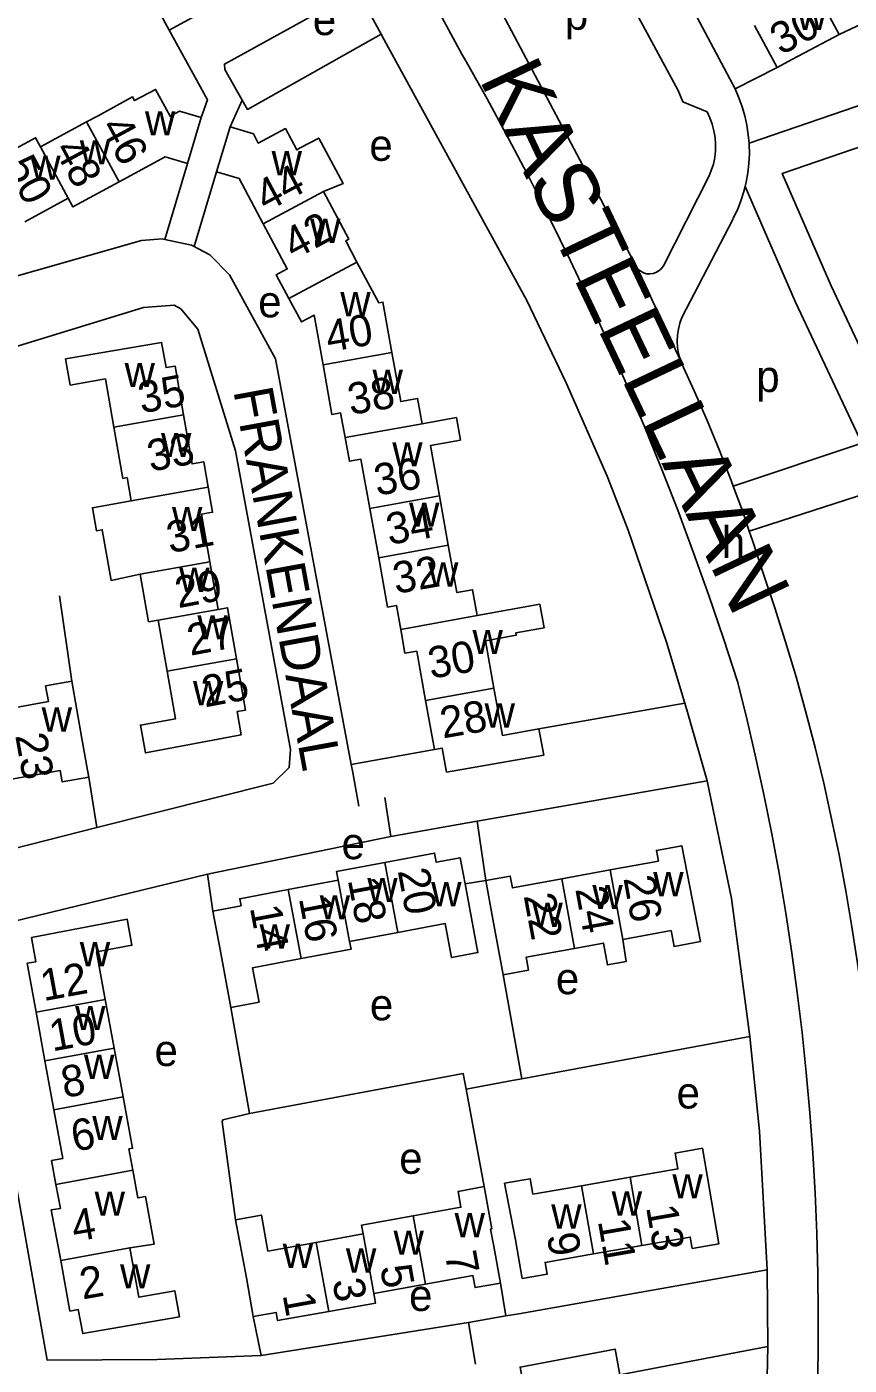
# Model space of a CAD drawing. Extents: x 157794 to 159375, y 380877 to 382306.
# Drawn here: x 158902.6 to 159007.2, y 381561.1 to 381731.3 of the extents above; entities that cross this region are included whole.
import ezdxf

# ---------------------------------------------------------------- set-up
doc = ezdxf.new("R2010")
doc.units = 0
for name, color, linetype in [('BLT_Basislijn', 7, 'Continuous'), ('BLT_Bebouwing', 7, 'Continuous'), ('BLT_Centroide', 7, 'Continuous'), ('BLT_Huisnummer', 7, 'Continuous'), ('BLT_Huisnummer_ tussenligend', 7, 'Continuous'), ('BLT_Onderverdeling_panden', 7, 'Continuous'), ('BLT_Straatnaam', 7, 'Continuous'), ('BLT_Straatnaam_hoofdweg', 7, 'Continuous'), ('BLT_Vlakafsluiter', 7, 'Continuous')]:
    doc.layers.add(name, color=color, linetype=linetype)

msp = doc.modelspace()

# ---------------------------------------------------------------- linework, layer by layer
at = {"layer": 'BLT_Basislijn'}
for p, q in [((158945.98, 381750), (158957.93, 381727.86)), ((158985.45, 381723.23), (158970.96, 381750)), ((158978.56, 381750), (158992.69, 381723.42)), ((158947.67, 381730.38), (158937.97, 381748.31)), ((159073.46, 381743.61), (158994.46, 381716.52)), ((158961.79, 381735.49), (158980.12, 381700.78)), ((159005.91, 381730.36), (159018.4, 381736.22)), ((158948.05, 381729.68), (158947.67, 381730.38)), ((158998.02, 381726.14), (158992.69, 381723.42)), ((158928.45, 381718.59), (158929.96, 381722.01)), ((158920.13, 381704.27), (158923, 381713.94)), ((158923.86, 381703.37), (158926.71, 381712.88)), ((158983.58, 381700.92), (158989.39, 381712.38)), ((158992.39, 381706.83), (158985.92, 381694.34)), ((159008.8, 381678.36), (158992.46, 381672.87)), ((159010.76, 381672.41), (158994.49, 381667.18)), ((158906.74, 381658.94), (158908.28, 381648.08)), ((158967.73, 381642.01), (158986.28, 381645.29)), ((158943.84, 381637.49), (158954.43, 381639.37)), ((158910.44, 381635.86), (158911.49, 381629.45)), ((158959.88, 381630.28), (158989.13, 381635.38)), ((158948.12, 381633.27), (158948.9, 381628.3)), ((158960.95, 381622.7), (158959.88, 381630.28)), ((158948.9, 381628.3), (158925.56, 381623.52)), ((158925.56, 381623.52), (158926.23, 381618.83)), ((158958.32, 381622.28), (158960.95, 381622.7)), ((158963.16, 381610.71), (158965.54, 381597.49)), ((158928.54, 381606.57), (158930.9, 381593.06)), ((158994.57, 381602.88), (158965.54, 381597.49)), ((158958.47, 381596.15), (158960.77, 381583.77)), ((158996.87, 381563.43), (158996.78, 381573.19)), ((158962.82, 381571.5), (158963.53, 381567.32)), ((158932.38, 381562.28), (158931.38, 381567.24)), ((158958.78, 381566.5), (158963.53, 381567.32)), ((158932.38, 381562.28), (158958.78, 381566.5)), ((158959.66, 381561.2), (158958.78, 381566.5)), ((158978.02, 381559.82), (158996.87, 381563.43))]:
    msp.add_line(p, q, dxfattribs=at)
for points in [[(159108.87, 381686.54), (159105.46, 381699.16), (159100.87, 381714.75), (159096.96, 381727.42), (159090, 381741.34), (159089.57, 381741.73), (159089.09, 381742.06), (159088.58, 381742.33), (159088.02, 381742.52), (159087.45, 381742.63), (159086.87, 381742.66), (159086.29, 381742.62), (159085.72, 381742.49), (159085.49, 381742.42), (159084.45, 381742.09), (158998.68, 381712.68), (159004.91, 381698.37), (159013.56, 381679.97)], [(158937.34, 381739.97), (158939.99, 381734.95), (158940.67, 381733.68), (158927.71, 381726.58), (158927.76, 381725.9), (158929.96, 381722.01)], [(158847.29, 381733.34), (158870.18, 381690.77), (158917.15, 381704.15), (158919.77, 381704.34), (158920.13, 381704.27)], [(158924.74, 381719.79), (158925.55, 381722.03), (158920.68, 381730.91)], [(158929.96, 381722.01), (158930.64, 381720.81), (158947.67, 381730.38)], [(158948.05, 381729.68), (158966.18, 381696.49), (158971.19, 381686.04), (158976.39, 381674.17), (158979.06, 381667.27), (158983.95, 381653.06), (158986.28, 381645.29)], [(158993.01, 381648.03), (158991.22, 381653.51), (158989.35, 381658.98), (158987.4, 381664.41), (158985.38, 381669.82), (158983.28, 381675.2), (158981.11, 381680.55), (158978.87, 381685.87), (158976.55, 381691.16), (158974.16, 381696.42), (158971.69, 381701.64), (158969.16, 381706.83), (158966.55, 381711.98), (158963.87, 381717.1), (158961.12, 381722.18), (158958.3, 381727.22), (158957.93, 381727.86)], [(158992.69, 381723.42), (158993.18, 381722.31), (158993.59, 381721.16), (158993.93, 381719.99), (158994.19, 381718.8), (158994.37, 381717.6), (158994.46, 381716.52)], [(158985.45, 381723.23), (158986.04, 381721.76), (158989.12, 381720.5)], [(158989.12, 381720.5), (158989.49, 381719.73), (158989.78, 381718.92), (158990, 381718.1), (158990.15, 381717.25), (158990.21, 381716.4), (158990.19, 381715.55), (158990.09, 381714.7), (158989.92, 381713.86), (158989.66, 381713.04), (158989.39, 381712.38)], [(158994.46, 381716.52), (158994.48, 381716.38), (158994.5, 381715.16), (158994.44, 381713.95), (158994.3, 381712.74), (158994.09, 381711.54), (158993.95, 381711)], [(158993.95, 381711), (158993.79, 381710.36), (158993.42, 381709.2), (158992.98, 381708.06), (158992.46, 381706.96), (158992.39, 381706.83)], [(158993.95, 381711), (159000.36, 381696.3), (159008.8, 381678.36)], [(158920.13, 381704.27), (158923.51, 381703.56), (158923.86, 381703.37)], [(158923.86, 381703.37), (158924.33, 381703.11), (158925.87, 381702.32), (158928.35, 381699.78), (158934.21, 381689.08), (158943.84, 381637.49)], [(158980.12, 381700.78), (158980.37, 381700.47), (158980.69, 381700.22), (158981.05, 381700.03), (158981.43, 381699.92), (158981.84, 381699.89), (158982.24, 381699.93), (158982.62, 381700.06), (158982.97, 381700.26), (158983.28, 381700.52), (158983.58, 381700.92)], [(158894.53, 381688.61), (158917.4, 381695.62), (158921.29, 381695.91), (158922.18, 381695.43), (158924.34, 381692.84), (158929.11, 381677.4), (158936.12, 381639.38), (158935.96, 381637.09), (158933.89, 381635.11), (158911.49, 381629.45)], [(158985.92, 381694.34), (158985.66, 381693.61), (158985.47, 381692.85), (158985.35, 381692.08), (158985.32, 381691.3), (158985.37, 381690.52), (158985.5, 381689.75), (158985.7, 381689), (158985.78, 381688.79)], [(158985.78, 381688.79), (158985.99, 381688.27), (158986.11, 381688)], [(158992.46, 381672.87), (158992.19, 381673.6), (158990.7, 381677.43), (158989.12, 381681.23), (158987.48, 381685), (158986.11, 381688)], [(158994.49, 381667.18), (158993.61, 381669.74), (158992.46, 381672.87)], [(158996.23, 381661.94), (158994.96, 381665.85), (158994.49, 381667.18)], [(158996.23, 381661.94), (158997.71, 381657.52), (158999.11, 381653.08), (159000.44, 381648.62), (159001.69, 381644.13), (159002.86, 381639.62), (159003.96, 381635.1), (159004.97, 381630.55), (159005.91, 381625.99), (159006.77, 381621.42), (159007.56, 381616.83), (159008.26, 381612.22), (159008.88, 381607.61), (159009.43, 381602.98), (159009.89, 381598.35), (159010.28, 381593.71), (159010.58, 381589.06), (159010.81, 381584.41), (159010.95, 381579.75), (159011.02, 381575.1), (159011.01, 381570.44), (159010.91, 381565.79), (159010.74, 381561.13), (159010.55, 381557.62)], [(159001.42, 381531.85), (159001.92, 381536.94), (159002.35, 381542.05), (159002.69, 381547.15), (159002.96, 381552.26), (159003.14, 381557.38), (159003.25, 381562.5), (159003.27, 381567.61), (159003.22, 381572.73), (159003.08, 381577.85), (159002.87, 381582.96), (159002.58, 381588.07), (159002.2, 381593.18), (159001.75, 381598.28), (159001.21, 381603.37), (159000.6, 381608.45), (158999.91, 381613.52), (158999.14, 381618.58), (158998.29, 381623.63), (158997.36, 381628.66), (158996.35, 381633.68), (158995.26, 381638.68), (158994.1, 381643.67), (158993.01, 381648.03)], [(158986.28, 381645.29), (158986.63, 381644.13), (158989.13, 381635.38)], [(158944.82, 381632.16), (158944.03, 381636.47), (158943.84, 381637.49)], [(158989.13, 381635.38), (158992.21, 381620.43), (158994.57, 381602.88)], [(158948.9, 381628.3), (158958.65, 381630.07), (158959.88, 381630.28)], [(158911.49, 381629.45), (158894.11, 381625.06), (158890.08, 381622.32), (158888.54, 381620.61), (158886.95, 381616.56), (158886.84, 381611.22), (158889.4, 381597.76), (158889.65, 381596.38)], [(158925.56, 381623.52), (158895.74, 381616.26), (158896.49, 381610.43), (158905.17, 381561.69), (158919.14, 381561.76), (158932.38, 381562.28)], [(158996.78, 381573.19), (158995.81, 381590.81), (158994.57, 381602.88)], [(158958.47, 381596.15), (158958.1, 381598.15), (158930.9, 381593.06)], [(158958.47, 381596.15), (158964.33, 381597.27), (158965.54, 381597.49)], [(158930.9, 381593.06), (158927.52, 381592.29), (158927.42, 381592.03), (158929.1, 381579.55)], [(158963.53, 381567.32), (158965.16, 381567.6), (158996.78, 381573.19)], [(158993.58, 381507.56), (158996.46, 381546.02), (158996.87, 381563.43)]]:
    msp.add_lwpolyline(points, dxfattribs=at)
at = {"layer": 'BLT_Bebouwing'}
for p, q in [((158937.34, 381739.97), (158920.68, 381730.91)), ((158995.17, 381731.5), (158998.02, 381726.14)), ((158910.17, 381719.23), (158904.3, 381716.05)), ((158924.74, 381719.79), (158923, 381713.94)), ((158928.45, 381718.59), (158926.71, 381712.88)), ((158907.84, 381709.52), (158902.31, 381706.53)), ((158956.19, 381665.38), (158955.06, 381671.65)), ((158946.21, 381670.05), (158947.34, 381663.78)), ((158926.9, 381657.2), (158925.84, 381663.25)), ((158920.4, 381649.35), (158919.26, 381655.85)), ((158953.3, 381645.63), (158954.43, 381639.37)), ((158970.62, 381622.93), (158976.77, 381624.06)), ((158935.82, 381621.56), (158942.17, 381622.76)), ((158943.64, 381614.95), (158949.79, 381616.11)), ((158912.54, 381607.59), (158913.68, 381601.39)), ((158904.87, 381599.77), (158903.73, 381605.97)), ((158913.68, 381601.39), (158914.82, 381595.18)), ((158906.01, 381593.56), (158904.87, 381599.77)), ((158973.15, 381583.89), (158979.32, 381584.96)), ((158939.4, 381576.68), (158945.35, 381577.76)), ((158974.66, 381575.21), (158980.83, 381576.28)), ((158953.3, 381571.37), (158946.72, 381570.18))]:
    msp.add_line(p, q, dxfattribs=at)
for points in [[(158917.24, 381737.24), (158918.29, 381735.31), (158920.68, 381730.91)], [(159005.91, 381730.36), (159003.57, 381734.78), (159003.07, 381735.71)], [(158998.02, 381726.14), (159000, 381727.2), (159005.91, 381730.36)], [(158924.74, 381719.79), (158922, 381720.6), (158920.8, 381719.95), (158918.95, 381723.37), (158916.28, 381721.93), (158916.03, 381722.4), (158911.63, 381720.02), (158910.17, 381719.23)], [(158940.32, 381710.36), (158942.8, 381711.38), (158939.71, 381717.16), (158937.36, 381715.91), (158936.9, 381715.67), (158935.46, 381718.37), (158932.02, 381716.54), (158931.4, 381717.69), (158928.45, 381718.59)], [(158904.3, 381716.05), (158903.67, 381717.21), (158898.15, 381714.22)], [(158923, 381713.94), (158920.17, 381714.78), (158914.3, 381711.6)], [(158914.3, 381711.6), (158908.43, 381708.42), (158907.84, 381709.52)], [(158926.71, 381712.88), (158929.57, 381712.01), (158932.64, 381706.26)], [(158944.57, 381701.4), (158943.14, 381704.09), (158943.54, 381704.31), (158940.32, 381710.36)], [(158932.64, 381706.26), (158935.7, 381700.52), (158934.31, 381699.77), (158935.9, 381696.78)], [(158949.02, 381689.91), (158947.87, 381696.3), (158947.34, 381696.21), (158944.57, 381701.4)], [(158935.9, 381696.78), (158937.5, 381693.79), (158939.11, 381694.65), (158940.25, 381688.33)], [(158913.64, 381680.38), (158912.56, 381686.53), (158908.09, 381685.74), (158907.5, 381689.08), (158919.72, 381691.17), (158920.28, 381687.97), (158921.42, 381688.17), (158922.51, 381681.94)], [(158952.86, 381680.83), (158952.28, 381684.04), (158950.15, 381683.65), (158949.02, 381689.91)], [(158940.25, 381688.33), (158941.39, 381682), (158942.49, 381682.2), (158943.07, 381679.07)], [(158925.64, 381672.76), (158925.08, 381675.97), (158923.6, 381675.71), (158922.51, 381681.94)], [(158955.06, 381671.65), (158953.91, 381678.05), (158957.74, 381678.74), (158957.22, 381681.62), (158952.86, 381680.83)], [(158915.85, 381671.04), (158915.33, 381673.98), (158914.79, 381673.88), (158913.64, 381680.38)], [(158943.07, 381679.07), (158943.62, 381676.06), (158945.08, 381676.32), (158946.21, 381670.05)], [(158925.84, 381663.25), (158924.77, 381669.31), (158926.2, 381669.56), (158925.64, 381672.76)], [(158917, 381661.7), (158913.3, 381660.89), (158912.17, 381667.35), (158911.42, 381667.22), (158910.91, 381670.14), (158915.85, 381671.04)], [(158959.88, 381656.43), (158959.29, 381659.7), (158957.28, 381659.34), (158956.19, 381665.38)], [(158947.34, 381663.78), (158948.47, 381657.51), (158949.59, 381657.71), (158950.14, 381654.67)], [(158919.26, 381655.85), (158918.06, 381655.64), (158917, 381661.7)], [(158929.25, 381650.9), (158928.11, 381657.41), (158926.9, 381657.2)], [(158967.86, 381657.87), (158959.88, 381656.43)], [(158961.99, 381647.2), (158960.91, 381653.21), (158964.84, 381653.92), (158964.79, 381654.23), (158968.4, 381654.88), (158967.86, 381657.87)], [(158950.14, 381654.67), (158950.68, 381651.63), (158952.17, 381651.89), (158953.3, 381645.63)], [(158929.25, 381650.9), (158930.4, 381644.39), (158929.31, 381644.2), (158929.83, 381641.24), (158917.65, 381638.94), (158917.02, 381642.5), (158921.47, 381643.28), (158920.4, 381649.35)], [(158899.03, 381644.35), (158905.3, 381645.48), (158904.94, 381647.48), (158908.28, 381648.08)], [(158908.28, 381648.08), (158909.55, 381640.78), (158910.28, 381636.75), (158910.44, 381635.86)], [(158967.73, 381642.01), (158963.08, 381641.17), (158961.99, 381647.2)], [(158954.43, 381639.37), (158955.42, 381639.55), (158955.97, 381636.51), (158968.33, 381638.65), (158967.73, 381642.01)], [(158910.44, 381635.86), (158907.07, 381635.26), (158906.81, 381636.71), (158900.6, 381635.6)], [(158976.77, 381624.06), (158982.93, 381625.19), (158982.68, 381626.55), (158985.9, 381627.14), (158988.28, 381614.94), (158984.92, 381614.32), (158984.55, 381616.35), (158978.4, 381615.21)], [(158948.11, 381625.02), (158941.96, 381623.86), (158942.17, 381622.76)], [(158948.11, 381625.02), (158954.44, 381626.21), (158954.66, 381625.04), (158957.69, 381625.61), (158958.32, 381622.28)], [(158960.95, 381622.7), (158964.08, 381623.28), (158964.36, 381621.78), (158970.62, 381622.93)], [(158926.23, 381618.83), (158929.83, 381619.51), (158929.66, 381620.4), (158935.82, 381621.56)], [(158949.79, 381616.11), (158955.81, 381617.24), (158956.62, 381612.92), (158959.96, 381613.54), (158958.62, 381620.7), (158958.32, 381622.28)], [(158963.16, 381610.71), (158961.86, 381617.79), (158960.95, 381622.7)], [(158903.16, 381615.46), (158915.34, 381617.78), (158915.94, 381614.49), (158911.43, 381613.66), (158912.54, 381607.59)], [(158928.54, 381606.57), (158927.16, 381613.92), (158926.23, 381618.83)], [(158903.73, 381605.97), (158902.6, 381612.18), (158903.72, 381612.39), (158903.16, 381615.46)], [(158937.48, 381612.78), (158943.83, 381613.98), (158943.64, 381614.95)], [(158972.25, 381614.08), (158975.93, 381614.76), (158976.44, 381611.98), (158978.84, 381612.42), (158978.4, 381615.21)], [(158928.54, 381606.57), (158932.11, 381607.24), (158931.28, 381611.61), (158937.48, 381612.78)], [(158963.16, 381610.71), (158966.4, 381611.32), (158966.1, 381612.95), (158972.25, 381614.08)], [(158914.82, 381595.18), (158916.02, 381588.65), (158915.56, 381588.57), (158916.06, 381585.85)], [(158906.27, 381584.05), (158905.71, 381587.09), (158907.15, 381587.36), (158906.01, 381593.56)], [(158979.32, 381584.96), (158985.41, 381586.02), (158985.06, 381588.05), (158988.52, 381588.66), (158990.63, 381576.5), (158987.24, 381575.91), (158986.99, 381577.35), (158980.83, 381576.28)], [(158916.06, 381585.85), (158916.7, 381582.33), (158917.66, 381582.5), (158918.77, 381576.47), (158915.67, 381575.98)], [(158906.87, 381574.36), (158905.68, 381580.8), (158906.83, 381581.01), (158906.27, 381584.05)], [(158951.73, 381580.05), (158957.79, 381581.15), (158957.43, 381583.17), (158960.77, 381583.77)], [(158960.77, 381583.77), (158961.74, 381578.41), (158961.58, 381578.38), (158961.93, 381576.42), (158962.82, 381571.5)], [(158973.15, 381583.89), (158966.96, 381582.82), (158966.62, 381584.77), (158963.36, 381584.2), (158964.74, 381577.01), (158965.6, 381572.08)], [(158929.1, 381579.55), (158932.41, 381580.15), (158933.24, 381575.57), (158939.4, 381576.68)], [(158931.38, 381567.24), (158930.5, 381572.16), (158929.1, 381579.55)], [(158945.35, 381577.76), (158945.15, 381578.87), (158951.73, 381580.05)], [(158915.67, 381575.98), (158916.83, 381569.69), (158921.38, 381570.53), (158921.98, 381567.22), (158909.67, 381565.07), (158909.11, 381568.12), (158908.05, 381567.93), (158906.87, 381574.36)], [(158965.6, 381572.08), (158968.76, 381572.63), (158968.5, 381574.14), (158974.66, 381575.21)], [(158962.82, 381571.5), (158959.61, 381570.92), (158959.33, 381572.46), (158953.3, 381571.37)], [(158946.72, 381570.18), (158946.94, 381568.96), (158940.99, 381567.89)], [(158940.99, 381567.89), (158934.48, 381566.72), (158934.29, 381567.76), (158931.38, 381567.24)], [(158978.02, 381559.82), (158977.41, 381563.11), (158965.33, 381560.82), (158965.89, 381557.81), (158964.76, 381557.6)]]:
    msp.add_lwpolyline(points, dxfattribs=at)
at = {"layer": 'BLT_Onderverdeling_panden'}
for p, q in [((158914.3, 381711.6), (158910.17, 381719.23)), ((158907.84, 381709.52), (158904.3, 381716.05)), ((158932.64, 381706.26), (158940.32, 381710.36)), ((158935.9, 381696.78), (158944.57, 381701.4)), ((158940.25, 381688.33), (158949.02, 381689.91)), ((158922.51, 381681.94), (158913.64, 381680.38)), ((158943.07, 381679.07), (158952.86, 381680.83)), ((158925.64, 381672.76), (158915.85, 381671.04)), ((158946.21, 381670.05), (158955.06, 381671.65)), ((158947.34, 381663.78), (158956.19, 381665.38)), ((158925.84, 381663.25), (158917, 381661.7)), ((158926.9, 381657.2), (158919.26, 381655.85)), ((158950.14, 381654.67), (158959.88, 381656.43)), ((158929.25, 381650.9), (158920.4, 381649.35)), ((158953.3, 381645.63), (158961.99, 381647.2)), ((158948.11, 381625.02), (158949.79, 381616.11)), ((158972.25, 381614.08), (158970.62, 381622.93)), ((158978.4, 381615.21), (158976.77, 381624.06)), ((158935.82, 381621.56), (158937.48, 381612.78)), ((158942.17, 381622.76), (158943.64, 381614.95)), ((158903.73, 381605.97), (158912.54, 381607.59)), ((158904.87, 381599.77), (158913.68, 381601.39)), ((158906.01, 381593.56), (158914.82, 381595.18)), ((158906.27, 381584.05), (158916.06, 381585.85)), ((158974.66, 381575.21), (158973.15, 381583.89)), ((158980.83, 381576.28), (158979.32, 381584.96)), ((158953.3, 381571.37), (158951.73, 381580.05)), ((158946.72, 381570.18), (158945.35, 381577.76)), ((158906.87, 381574.36), (158915.67, 381575.98)), ((158940.99, 381567.89), (158939.4, 381576.68))]:
    msp.add_line(p, q, dxfattribs=at)
at = {"layer": 'BLT_Vlakafsluiter'}
msp.add_line((158980.12, 381700.78), (158985.78, 381688.79), dxfattribs=at)

# ---------------------------------------------------------------- texts
at = {"layer": 'BLT_Centroide'}
for s, p in [('p', (158971.03, 381730.95)), ('w', (159000.54, 381730.94)), ('e', (158938.95, 381730.27)), ('w', (158917.59, 381717.5)), ('w', (158909.3, 381713.83)), ('e', (158946.15, 381714.27)), ('w', (158903, 381711.88)), ('w', (158933.71, 381712.44)), ('w', (158938.61, 381703.83)), ('e', (158932, 381694.36)), ('w', (158942.45, 381694.5)), ('w', (158915, 381685.5)), ('w', (158946.55, 381684.62)), ('p', (158995.38, 381684.86)), ('w', (158919.64, 381676.58)), ('w', (158949.06, 381675.41)), ('w', (158951.2, 381667.72)), ('w', (158921.03, 381667.17)), ('h', (158991, 381663.76)), ('w', (158921.95, 381659.44)), ('w', (158953.61, 381660.11)), ('w', (158924.26, 381653.38)), ('w', (158959.27, 381651.52)), ('w', (158923.7, 381645.02)), ('w', (158960.81, 381642.17)), ('w', (158904.45, 381641.66)), ('e', (158942.61, 381625.43)), ('w', (158945.88, 381619.98)), ('w', (158982.27, 381620.72)), ('w', (158954.01, 381619.44)), ('w', (158974.52, 381619.08)), ('w', (158939.83, 381617.77)), ('w', (158966.89, 381616.81)), ('w', (158932.18, 381614.06)), ('w', (158909.3, 381611.81)), ('e', (158969.88, 381608.25)), ('e', (158946.21, 381604.93)), ('w', (158908.71, 381603.69)), ('e', (158918.81, 381599.11)), ('w', (158909.84, 381597.47)), ('e', (158985.24, 381593.71)), ('w', (158910.89, 381589.69)), ('e', (158949.95, 381585.4)), ('w', (158984.7, 381582.28)), ('w', (158911.19, 381580.06)), ('w', (158976.98, 381580.09)), ('w', (158956.99, 381577.34)), ('w', (158969.29, 381578.44)), ('w', (158949.22, 381575.11)), ('w', (158935.12, 381573.44)), ('w', (158943.17, 381572.83)), ('w', (158914.42, 381570.83)), ('e', (158951.2, 381567.95))]:
    msp.add_text(s, height=4, dxfattribs=at).set_placement(p)
at = {"layer": 'BLT_Huisnummer'}
for s, rotation, p in [('30', 28.1092, (158998.52, 381727.65)), ('46', 298.427, (158911.85, 381718.62)), ('50', 298.427, (158899.69, 381713.6)), ('44', 28.0756, (158933, 381707.7)), ('40', 9.8363, (158940.96, 381689.93)), ('35', 10.6901, (158917.14, 381682.12)), ('36', 9.8363, (158947.11, 381671.65)), ('32', 9.8363, (158949.5, 381659.17)), ('29', 10.6901, (158921.82, 381657.35)), ('25', 10.6901, (158925.22, 381644.73)), ('28', 9.8363, (158955.5, 381640.78)), ('23', 280.1971, (158901.07, 381641.17)), ('20', 280.6628, (158949.74, 381623.96)), ('26', 280.4188, (158978.46, 381623.02)), ('22', 280.4257, (158965.77, 381620.78)), ('14', 280.6564, (158930.93, 381619.28)), ('12', 10.4039, (158904.69, 381607.36)), ('6', 10.4063, (158908.59, 381588.2)), ('13', 279.8675, (158981.34, 381581.16)), ('9', 279.8673, (158968.7, 381577.6)), ('7', 280.2242, (158955.74, 381575.24)), ('2', 9.8962, (158909.65, 381569.41)), ('1', 280.229, (158935.1, 381570.01))]:
    msp.add_text(s, height=4, rotation=rotation, dxfattribs=at).set_placement(p)
at = {"layer": 'BLT_Huisnummer_ tussenligend'}
for s, rotation, p in [('48', 298.427, (158905.96, 381715.75)), ('42', 28.0756, (158936.55, 381701.64)), ('38', 9.8363, (158943.75, 381681.93)), ('33', 10.6901, (158918.29, 381674.71)), ('31', 10.6901, (158920.75, 381664.34)), ('34', 9.8363, (158948.65, 381665.4)), ('27', 10.6901, (158923.36, 381651.3)), ('30', 9.8363, (158953.98, 381648.37)), ('18', 280.6564, (158943.39, 381622.81)), ('24', 280.4257, (158972.34, 381621.64)), ('16', 280.6564, (158937.16, 381620.46)), ('10', 10.4063, (158905.81, 381600.96)), ('8', 10.4063, (158907.32, 381595.04)), ('4', 9.8962, (158908.62, 381576.74)), ('11', 279.8673, (158975.21, 381579.41)), ('5', 280.2242, (158947.49, 381573.54)), ('3', 280.229, (158941.42, 381571.8))]:
    msp.add_text(s, height=4, rotation=rotation, dxfattribs=at).set_placement(p)
at = {"layer": 'BLT_Straatnaam'}
msp.add_text('FRANKENDAAL', height=4.9999, rotation=280.3597, dxfattribs=at).set_placement((158928.83, 381685.04))
at = {"layer": 'BLT_Straatnaam_hoofdweg'}
msp.add_text('KASTEELLAAN', height=8, rotation=295.4183, dxfattribs=at).set_placement((158960.05, 381724.72))

doc.saveas('drawing.dxf')
